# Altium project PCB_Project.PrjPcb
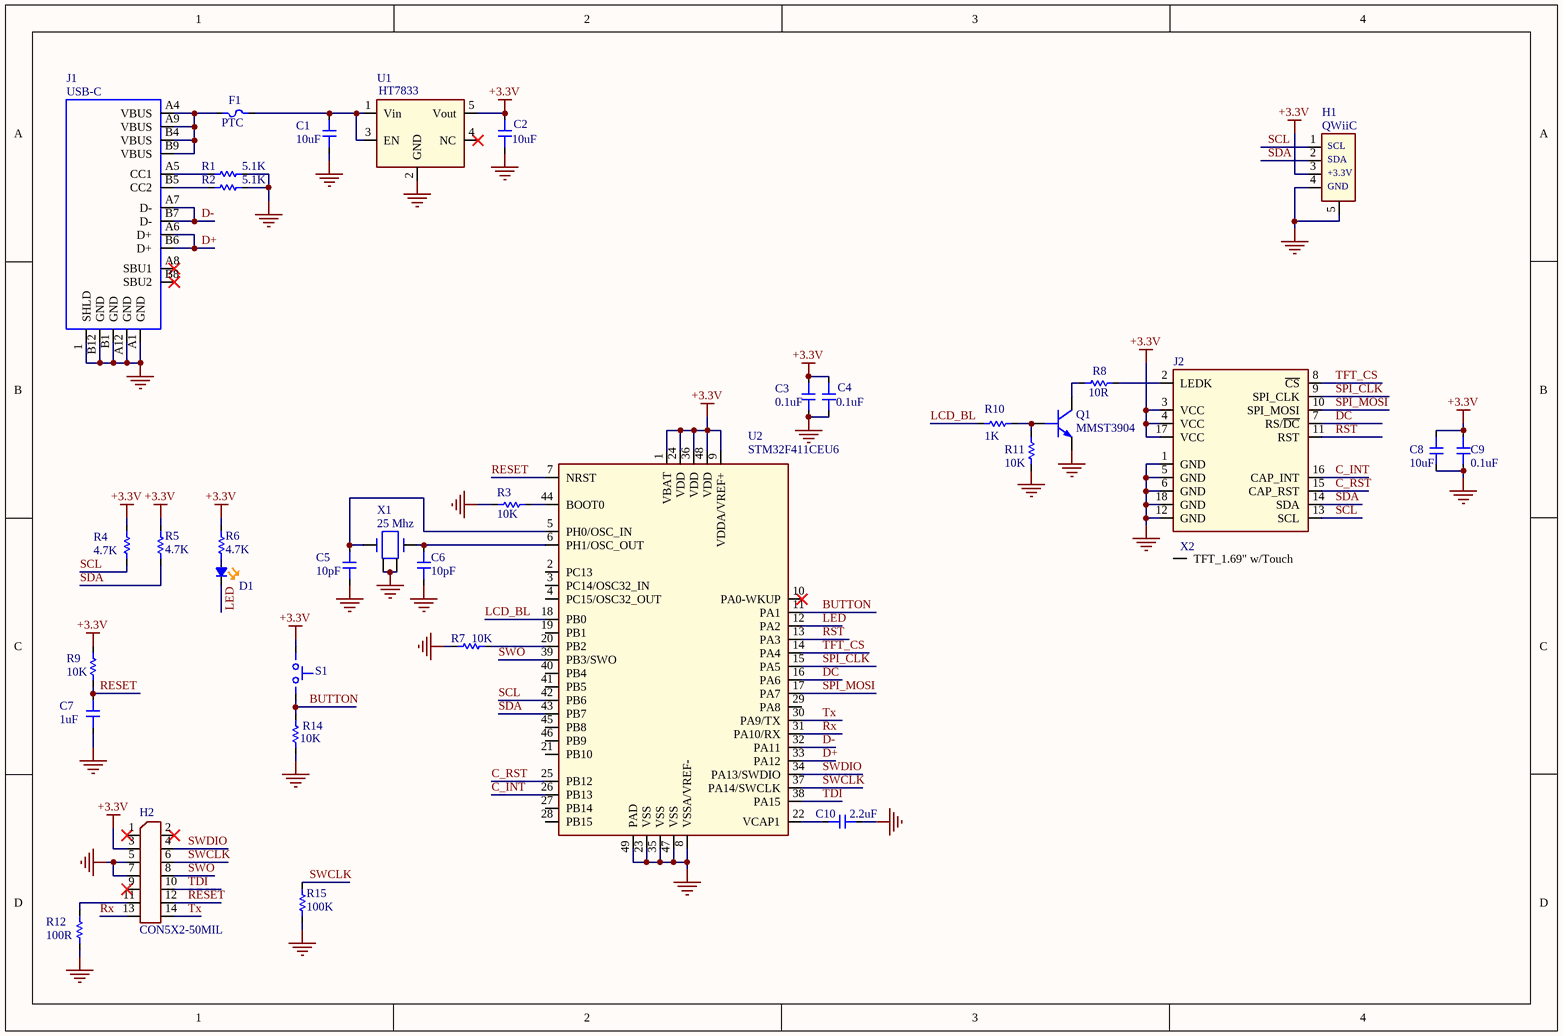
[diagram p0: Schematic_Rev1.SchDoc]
1 sheet, 36 parts. Net scope: global (net labels, ports and power ports of the same name join across sheets).
Board file: PCB1.PcbDoc

## Sheet Schematic_Rev1.SchDoc
size A4; Revision: 4; SheetNumber: 1; SheetTotal: 1

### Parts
C1  10uF  [CAPC2012X140N]
C2  10uF  [CAPC2012X140N]
C3  0.1uF  [CAPC1005X56N]
C4  0.1uF  [CAPC1005X56N]
C5  10pF  [CAPC1005X56N]
C6  10pF  [CAPC1005X56N]
C7  1uF  [CAPC1005X56N]
C8  10uF  [CAPC2012X140N]
C9  0.1uF  [CAPC1608X09L]
C10  2.2uF  [CAPC1608X09L]
D1  (no value)  [LED1005X40N-Orange]
F1  PTC  [RESC1608X06L (0603 FOOTPRINT)]
H1  QWiiC  [SM04B-SRSS-TB]
H2  CON5X2-50MIL  [HDR7X2-50MIL]
J1  USB-C  [TYPE-C-31-M-12]
J2  (no value)  [TFT_GLASS 1.69 INCH SPI CAP TOUCH]
Q1  MMST3904  [SC-70]
R1  5.1K  [RESC1005X40L (0402 FOOTPRINT)]
R2  5.1K  [RESC1005X40L (0402 FOOTPRINT)]
R3  10K  [RESC1005X40L (0402 FOOTPRINT)]
R4  4.7K  [RESC1005X40L (0402 FOOTPRINT)]
R5  4.7K  [RESC1005X40L (0402 FOOTPRINT)]
R6  4.7K  [RESC1005X40L (0402 FOOTPRINT)]
R7  10K  [RESC1005X40L (0402 FOOTPRINT)]
R8  10R  [RESC1005X40L (0402 FOOTPRINT)]
R9  10K  [RESC1005X40L (0402 FOOTPRINT)]
R10  1K  [RESC1005X40L (0402 FOOTPRINT)]
R11  10K  [RESC1005X40L (0402 FOOTPRINT)]
R12  100R  [RESC1005X40L (0402 FOOTPRINT)]
R14  10K  [RESC1005X40L (0402 FOOTPRINT)]
R15  100K  [RESC1005X40L (0402 FOOTPRINT)]
S1  (no value)  [TS-1088R-02526]
U1  HT7833  [SOT95P280X144-5N]
U2  STM32F411CEU6  [QFN48_NEWEST 0.5mm pitch]
X1  25 Mhz  [OSC20X16]
X2  TFT_1.69" w/Touch  (value not drawn)

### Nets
+3.3V: C2.1 C3.2 C4.2 C8.1 C9.1 H1.3 H2.3 J2.3(VCC) J2.4(VCC) J2.17(VCC) R4.1 R5.1 R6.1 R9.1 S1.1(A) U1.5(Vout) U2.1(VBAT) U2.9(VDDA/VREF+) U2.24(VDD) U2.36(VDD) U2.48(VDD)
GND: C1.2 C2.2 C3.1 C4.1 C5.1 C6.1 C7.1 C8.2 C9.2 C10.2 H1.4 H1.5 H2.5 H2.7 J1.1(SHLD) J1.A1(GND) J1.A12(GND) J1.B1(GND) J1.B12(GND) J2.1(GND) J2.5(GND) J2.6(GND) J2.12(GND) J2.18(GND) Q1.2(E) R1.1 R2.1 R3.1 R7.1 R11.2 R12.2 R14.1 R15.2 U1.2(GND) U2.8(VSSA/VREF-) U2.23(VSS) U2.35(VSS) U2.47(VSS) U2.49(PAD) X1.2 X1.4
BUTTON: R14.2 S1.2(B) U2.11(PA1)
C_INT: J2.16(CAP_INT) U2.26(PB13)
C_RST: J2.15(CAP_RST) U2.25(PB12)
D+: J1.A6(D+) J1.B6(D+) U2.33(PA12)
D-: J1.A7(D-) J1.B7(D-) U2.32(PA11)
DC: J2.7(RS/~{DC}) U2.16(PA6)
LCD_BL: R10.2 U2.18(PB0)
LED: D1.1 U2.12(PA2)
RESET: C7.2 H2.12 R9.2 U2.7(NRST)
RST: J2.11(RST) U2.13(PA3)
Rx: H2.13 U2.31(PA10/RX)
SCL: H1.1 J2.13(SCL) R4.2 U2.42(PB6)
SDA: H1.2 J2.14(SDA) R5.2 U2.43(PB7)
SPI_CLK: J2.9(SPI_CLK) U2.15(PA5)
SPI_MOSI: J2.10(SPI_MOSI) U2.17(PA7)
SWCLK: H2.6 R15.1 U2.37(PA14/SWCLK)
SWDIO: H2.4 U2.34(PA13/SWDIO)
SWO: H2.8 U2.39(PB3/SWO)
TDI: H2.10 U2.38(PA15)
TFT_CS: J2.8(~{CS}) U2.14(PA4)
Tx: H2.14 U2.30(PA9/TX)
NetC1_1: C1.1 F1.1 U1.1(Vin) U1.3(EN)
NetC5_2: C5.2 U2.5(PH0/OSC_IN) X1.1
NetC6_2: C6.2 U2.6(PH1/OSC_OUT) X1.3
NetC10_1: C10.1 U2.22(VCAP1)
NetD1_2: D1.2 R6.2
NetF1_2: F1.2 J1.A4(VBUS) J1.A9(VBUS) J1.B4(VBUS) J1.B9(VBUS)
NetH2_11: H2.11 R12.1
NetJ1_A5: J1.A5(CC1) R1.2
NetJ1_B5: J1.B5(CC2) R2.2
NetJ2_2: J2.2(LEDK) R8.1
NetQ1_1: Q1.1(B) R10.1 R11.1
NetQ1_3: Q1.3(C) R8.2
NetR3_2: R3.2 U2.44(BOOT0)
NetR7_2: R7.2 U2.20(PB2)

Not connected (* = marked no-connect by the designer): H2 1* 2* 9*; J1 A8(SBU1)* B8(SBU2)*; U1 4(NC)*; U2 2(PC13) 3(PC14/OSC32_IN) 4(PC15/OSC32_OUT) 10(PA0-WKUP)* 19(PB1) 21(PB10) 27(PB14) 28(PB15) 29(PA8) 40(PB4) 41(PB5) 45(PB8) 46(PB9); X2 1(TFT_1.69"_w/Touch)

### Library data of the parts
C1 C2 C8 = CAP_0805: CAP 10uF 0805; Part_Footprint: 0805
C3 C4 = CAP_0402: CAP 0.1uF 0402; Part_Footprint: 0402
C5 C6 = CAP_0402: CAP 10pF 0402; Part_Footprint: 0402
C7 = CAP_0402: CAP 1uF 0402; Part_Footprint: 0402
C9 = CAP_0603: CAP 0.1uF 0603; Part_Footprint: 0603
C10 = CAP_0603: CAP 2.2uF 0603; Part_Footprint: 0603
D1 = LED_0402_SMALL_Orange: LED Orange 0402; Manufacturer: Lite-On; Part_Number: C364554; Part_Footprint: 0402; Vendor: LCSC
F1 = PTC_FUSE_0603: PTC FUSE 0.5mA hold, 1A trip 0603; Manufacturer: JDT Fuse; Part_Number: C2982257; Vendor: LCSC
H1 = SM04B-SRSS-TB: CONN HEADER 4POS .100 R/A QWIIC; Manufacturer: JST; Part_Number: PRT-14417; Vendor: Digi-Key
H2 = CON7X2_50mil: JTAG CONN HEADER 7X2POS 50mil" PADS
J1 = USB-C: CONN RECPT USB-C; Manufacturer: KHE; Part_Number: C165948; Part_Footprint: SMT; Vendor: LCSC
J2 = 0527451897: CONN BOTTOM 18POS 0.5MM R/A; Part_Number: 5051101892; Manufacturer: Molex; Vendor: Digi-Key
Q1 = MMST3904: TRANSISTOR NPN GP 40V SC-70; Manufacturer: Changjiang; Part_Number: C54879; Vendor: LCSC
R1 R2 = RES_0402: RES 5.1K 0402; Part_Footprint: 0402
R3 R7 R9 R11 R14 = RES_0402: RES 10K 0402; Part_Footprint: 0402
R4-R6 = RES_0402: RES 4.7K 0402; Part_Footprint: 0402
R8 = RES_0402: RES 10R 0402; Part_Footprint: 0402
R10 = RES_0402: RES 1K 0402; Part_Footprint: 0402
R12 = RES_0402: RES 100R 0402; Part_Footprint: 0402
R15 = RES_0402: RES 100K 0402; Part_Footprint: 0402
S1 = TS-1088R-02526: Tactile Micro Switch; Part_Number: C455281; Manufacturer: XUNPU; Part_Footprint: SMD; Vendor: LCSC
U1 = HT7833: IC LDO 3.3V 0.5A SOT23-5; Manufacturer: Holtek; Part_Number: C164106; Vendor: LCSC
U2 = STM32F411CEU6: IC MCU 32BIT 512KB FLASH 48LQFN; Manufacturer: ST Micro
X1 = 25Mhz: CRYSTAL 25MHZ 10PF SMD; Part_Number: ECS-250-10-37B2-CTN-TR; Manufacturer: ECS; Vendor: Digi-Key
X2 = TFT_GLASS 1.69 INCH COLOR SPI_CAP_TOUCH_COLOR: 1.69 INCH TFT SPI GLASS COLOR ROUNDED CORNERS, CAPACITIVE TOUCH; Part_Number: P169H002-CTP; Vendor: Aliexpress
